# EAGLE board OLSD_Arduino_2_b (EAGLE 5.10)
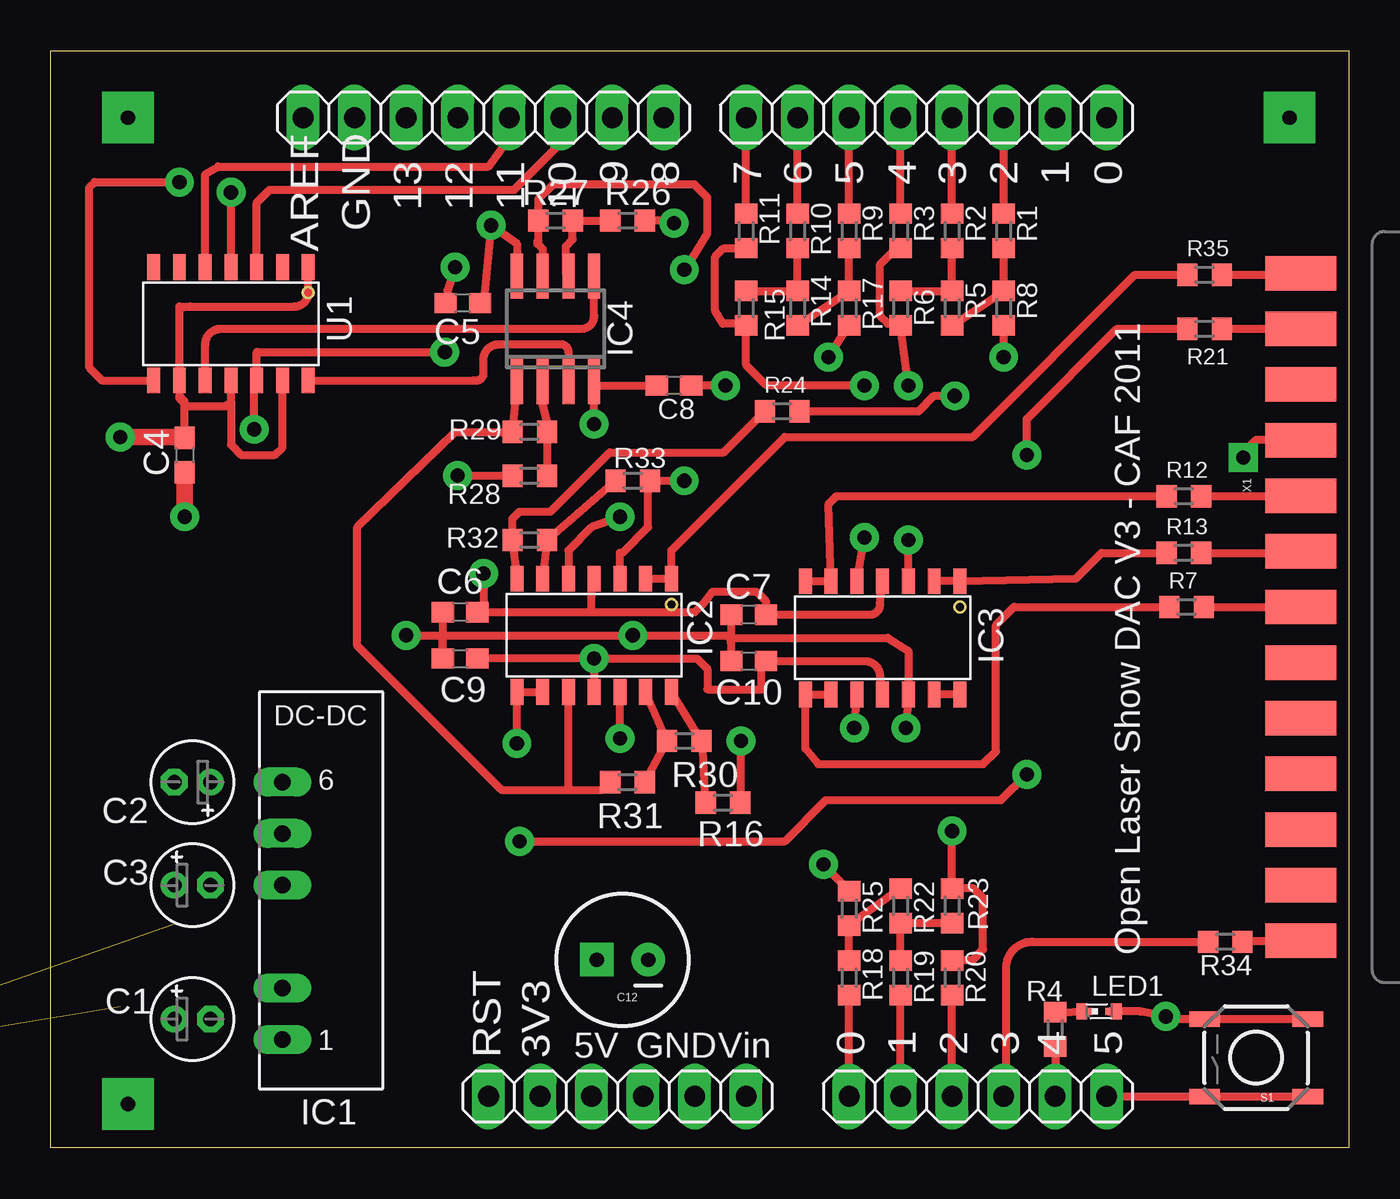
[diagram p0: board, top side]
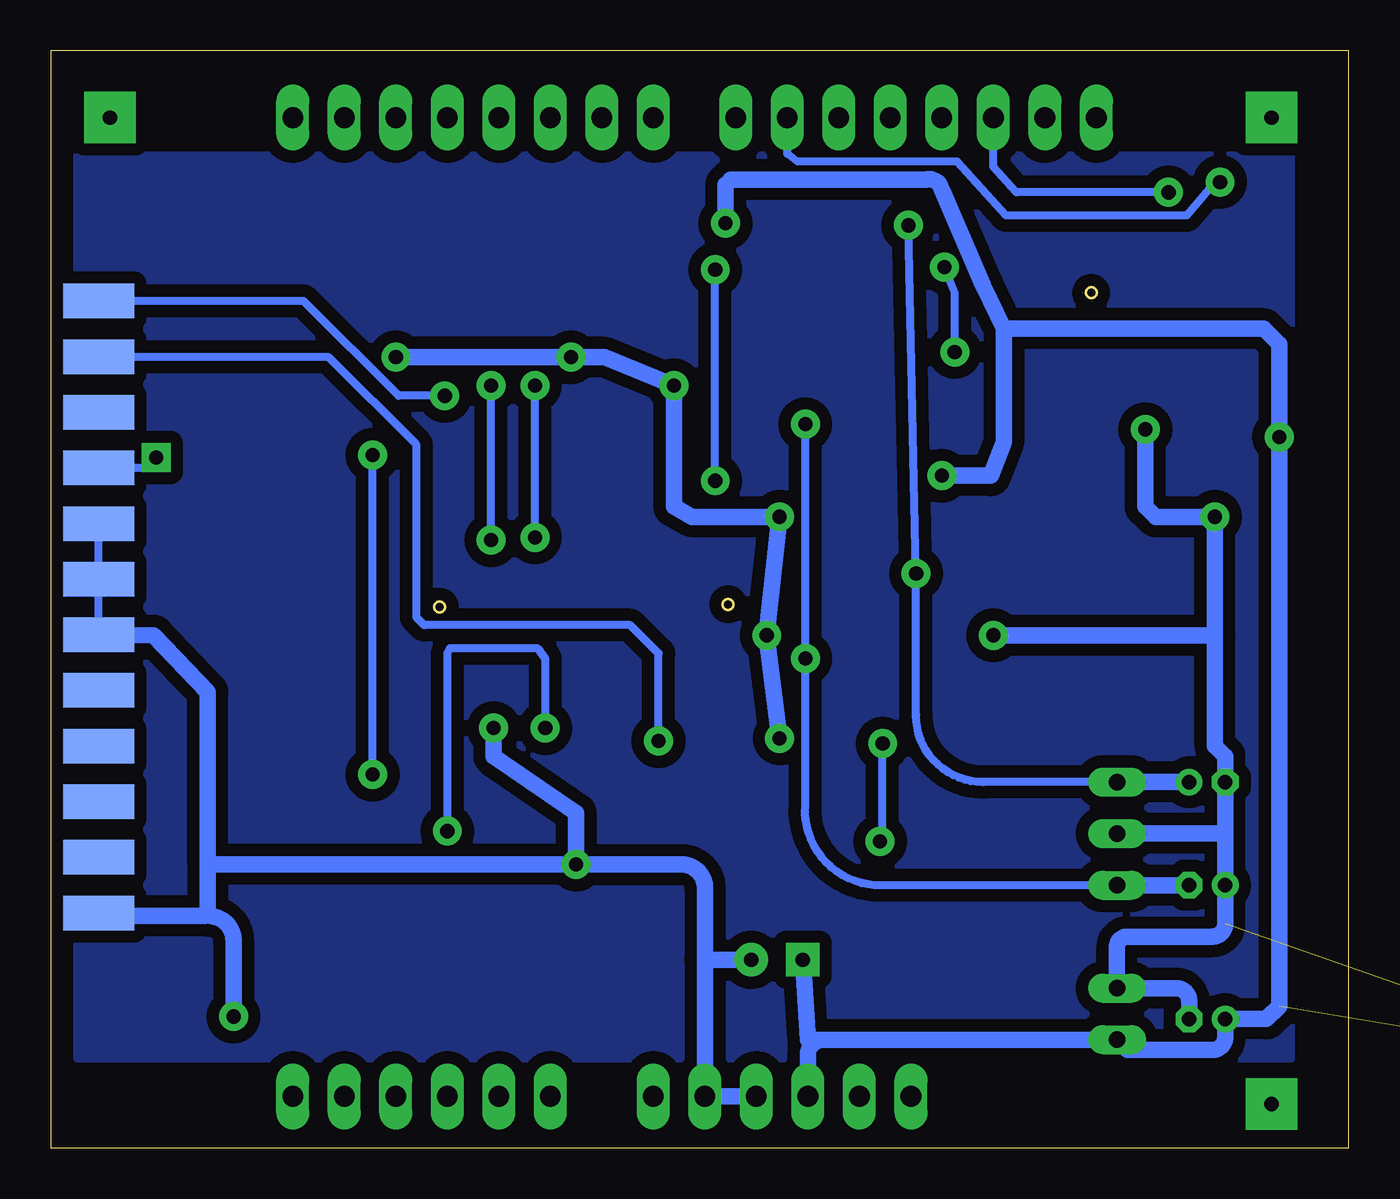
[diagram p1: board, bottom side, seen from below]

Size 64.01 x 54.1 mm. Coordinates in mm from the lower left corner, seen from the top.
Outline: 0,54.1 64.01,54.1 64.01,0 0,0 0,54.1
Copper layers (1*16): Top 0.035mm / dielectric 1.5mm / Bottom 0.035mm
Design rules "SparkFun": minimum track width 8mil, minimum drill 20mil, track to track 8mil, track to pad 8mil, pad to pad 8mil, via to via 8mil, smd to smd 8mil, copper to edge 10mil, drill to drill 8mil, minimum pad ring 12mil, minimum via ring 10mil, stop-mask expansion 4mil, vias tented up to drill 25mil, thermal gap 10mil

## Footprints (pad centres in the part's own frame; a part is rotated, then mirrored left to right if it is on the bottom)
E1,8-4 = drill 0.711 pad 1.168 round: + -0.889,0 | drill 0.711 pad 1.168 octagon: - 0.889,0
C0603 = smd 1.1 x 1: 1 -0.85,0; 2 0.85,0
CPOL-RADIAL-100UF-25V = drill 0.7 pad 1.651 square: 1 1.27,0 | drill 0.7 pad 1.651 round: 2 -1.27,0
NMA = drill 0.813 long: 1 0,6.35; 2 0,3.81; 4 0,-1.27; 5 0,-3.81; 6 0,-6.35
SOIC-14 = smd 1.27 x 0.635: 1 -0.762,-0.508; 2 -0.762,-1.778; 3 -0.762,-3.048; 4 -0.762,-4.318; 5 -0.762,-5.588; 6 -0.762,-6.858; 7 -0.762,-8.128; 8 4.826,-8.128; 9 4.826,-6.858; 10 4.826,-5.588; 11 4.826,-4.318; 12 4.826,-3.048; 13 4.826,-1.778; 14 4.826,-0.508
SO08 = smd 0.6 x 2.2: 1 -1.905,-2.6; 2 -0.635,-2.6; 3 0.635,-2.6; 4 1.905,-2.6; 5 1.905,2.6; 6 0.635,2.6; 7 -0.635,2.6; 8 -1.905,2.6
SMARTLED-TTW = smd 0.8 x 0.5: A 0,-0.875; C 0,0.875 | smd 0.35 x 0.35: A@1 0,-0.5; C@1 0,0.5
R0603 = smd 1 x 1.1: 1 -0.85,0; 2 0.85,0
TACTILE_SWITCH_SMD = smd 1.524 x 0.762: 1 -2.54,1.905; 2 2.54,1.905; 3 -2.54,-1.905; 4 2.54,-1.905
1X06 = drill 1.016 long: 1 -6.35,0; 2 -3.81,0; 3 -1.27,0; 4 1.27,0; 5 3.81,0; 6 6.35,0
1X08 = drill 1.016 long: 1 -8.89,0; 2 -6.35,0; 3 -3.81,0; 4 -1.27,0; 5 1.27,0; 6 3.81,0; 7 6.35,0; 8 8.89,0
F25D = smd 1.7 x 3.5: 1 -16.459,-6.045; 2 -13.716,-6.045; 3 -10.973,-6.045; 4 -8.23,-6.045; 5 -5.486,-6.045; 6 -2.743,-6.045; 7 0,-6.045; 8 2.743,-6.045; 9 5.486,-6.045; 10 8.23,-6.045; 11 10.973,-6.045; 12 13.716,-6.045; 13 16.459,-6.045 | smd 1.7 x 3.5 bottom: 14 -15.088,-6.045; 15 -12.344,-6.045; 16 -9.601,-6.045; 17 -6.858,-6.045; 18 -4.115,-6.045; 19 -1.372,-6.045; 20 1.372,-6.045; 21 4.115,-6.045; 22 6.858,-6.045; 23 9.601,-6.045; 24 12.344,-6.045; 25 15.088,-6.045

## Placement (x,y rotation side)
C1  4.7uF  [E1,8-4]  6.99,6.35 0 top
C2  4.7uF  [E1,8-4]  6.99,18.03 180 top
C3  4.7uF  [E1,8-4]  6.99,12.95 0 top
C4  0.1uF  [C0603]  6.6,34.16 270 top
C5  0.1uF  [C0603]  20.32,41.66 180 top
C6  0.1uF  [C0603]  20.19,26.42 180 top
C7  0.1uF  [C0603]  34.42,26.29 180 top
C8  0.1uF  [C0603]  30.73,37.59 180 top
C9  0.1uF  [C0603]  20.19,24.13 0 top
C10  0.1uF  [C0603]  34.42,24 0 top
C11  2200uF  [CPOL-RADIAL-100UF-25V]  not placed on the board
C12  100uF  [CPOL-RADIAL-100UF-25V]  28.19,9.27 180 top
IC1  VASD1-SIP  [NMA]  11.43,11.68 180 top
IC2  TL084  [SOIC-14]  31.12,27.3 270 top
IC3  TL084  [SOIC-14]  45.34,27.18 270 top
IC4  TL082D  [SO08]  24.89,40.39 0 top
LED1  Green  [SMARTLED-TTW]  51.69,6.73 270 top
R1  20K  [R0603]  46.99,45.21 270 top
R2  20K  [R0603]  44.45,45.21 270 top
R3  20K  [R0603]  41.91,45.21 270 top
R4  1K  [R0603]  49.53,5.84 90 top
R5  10K  [R0603]  44.45,41.4 270 top
R6  10K  [R0603]  41.91,41.4 90 top
R7  75R  [R0603]  56.01,26.67 0 top
R8  20K  [R0603]  46.99,41.4 270 top
R9  20K  [R0603]  39.37,45.21 270 top
R10  20K  [R0603]  36.83,45.21 270 top
R11  20K  [R0603]  34.29,45.21 270 top
R12  75R  [R0603]  55.88,32.13 0 top
R13  75R  [R0603]  55.88,29.34 0 top
R14  10K  [R0603]  36.83,41.4 270 top
R15  10K  [R0603]  34.29,41.4 90 top
R16  75R  [R0603]  33.15,17.02 0 top
R17  20K  [R0603]  39.37,41.4 270 top
R18  20K  [R0603]  39.37,8.38 90 top
R19  20K  [R0603]  41.91,8.38 90 top
R20  20K  [R0603]  44.45,8.38 90 top
R21  75R  [R0603]  56.9,40.39 0 top
R22  10K  [R0603]  41.91,11.94 90 top
R23  10K  [R0603]  44.45,11.94 270 top
R24  75R  [R0603]  36.07,36.32 0 top
R25  20K  [R0603]  39.37,11.81 90 top
R26  10K  [R0603]  28.45,45.72 180 top
R27  10K  [R0603]  24.89,45.72 180 top
R28  10K  [R0603]  23.62,33.15 0 top
R29  10K  [R0603]  23.62,35.31 180 top
R30  10K  [R0603]  31.24,20.07 0 top
R31  10K  [R0603]  28.45,18.03 0 top
R32  10K  [R0603]  23.62,29.97 180 top
R33  10K  [R0603]  28.7,32.89 180 top
R34  1K  [R0603]  57.91,10.16 0 top
R35  75R  [R0603]  56.9,43.05 0 top
S1  MINI 6X6MM SMD GW  [TACTILE_SWITCH_SMD]  59.44,4.45 180 top
U1  MCP4922  [SOIC-14]  13.21,42.67 270 top
U$1  POWER  [1X06]  27.94,2.54 0 top
U$2  ANALOG  [1X06]  45.72,2.54 0 top
U$3  DIGITAL_0_7  [1X08]  43.18,50.8 0 top
U$4  DIGITAL_8_13  [1X08]  21.34,50.8 0 top
X1  ILDA 25 Pin  [F25D]  67.69,26.67 270 top

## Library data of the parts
C1-C3 = rcl
C4-C10 = adafruit
C11 C12 S1 X1 = SparkFun
IC1 = dc-dc-converter
IC2 IC3 U1 = favreau
IC4 = linear
LED1 = led
R1-R35 = resistor
U$1-U$4 = arduino

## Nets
#LDAC: U1.8 U$4.7
+5V: C1.+ C4.1 C11.1 C12.1 IC1.1 R26.1 R28.1 U1.1 U1.9 U1.11 U1.13 U$1.3
+12V: C2.+ C5.1 C6.1 C7.1 IC1.6 IC2.4 IC3.4 IC4.8
-12V: C3.- C8.2 C9.2 C10.2 IC1.4 IC2.11 IC3.11 IC4.4
B1+: IC3.8 IC3.9 R7.1
B+: R7.2 X1.7
BLUE1: IC3.10 R20.2 R23.1
G1+: IC3.1 IC3.2 R13.1
G+: R13.2 X1.6
GND: C1.- C2.- C3.+ C4.2 C5.2 C6.2 C7.2 C8.1 C9.1 C10.1 C11.2 C12.2 IC1.2 IC1.5 IC2.5 IC2.12 IC3.12 LED1.C@1 R8.2 R17.2 R25.2 S1.3 S1.4 U1.12 U$1.4 U$1.5 X1.18 X1.19 X1.20 X1.25
GREEN1: IC3.3 R3.2 R6.1
INTERLOCK: X1.4 X1.17
MOSI: U1.5 U$4.5
N$1: R2.1 U$3.5
N$2: R9.1 U$3.3
N$3: R2.2 R5.1 R6.2
N$4: R1.1 U$3.6
N$5: R1.2 R5.2 R8.1
N$6: R3.1 U$3.4
N$7: R10.1 U$3.2
N$8: R11.1 U$3.1
N$9: R10.2 R14.1 R15.2
N$10: R9.2 R14.2 R17.1
N$11: R18.1 U$2.1
N$12: R19.1 U$2.2
N$13: R4.1 U$2.5
N$14: R19.2 R22.1 R23.2
N$15: R18.2 R22.2 R25.1
N$16: R20.1 U$2.3
N$17: R34.1 U$2.4
N$18: S1.1 S1.2 U$2.6
N$20: LED1.A@1 R4.2
N$24: IC4.5 U1.10
N$29: IC3.13 IC3.14
N$30: IC4.6 R26.2 R27.1
N$31: IC4.2 R28.2 R29.1
N$33: IC4.3 U1.14
N$35: IC2.6 R32.1 R33.2
N$36: IC2.13 R30.1 R31.2
R1+: IC3.6 IC3.7 R12.1
R+: R12.2 X1.5
RED1: IC3.5 R11.2 R15.1
SCK: U1.4 U$4.3
SHUTTER: R34.2 X1.13
SS: U1.3 U$4.6
X1+: IC2.1 IC2.2 R35.1
X1-: IC2.7 R24.1 R32.2
X2: IC2.10 IC4.1 R29.2 R31.1
X+: R35.2 X1.1
X-: R24.2 X1.14
Y1+: IC2.8 IC2.9 R21.1
Y1-: IC2.14 R16.1 R30.2
Y2: IC2.3 IC4.7 R27.2 R33.1
Y+: R21.2 X1.2
Y-: R16.2 X1.15

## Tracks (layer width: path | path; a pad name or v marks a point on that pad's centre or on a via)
#LDAC  (via drill 0.7 pad 1.42)
  Top 0.406: U1.8 2.54,37.85 1.91,38.48 1.91,47.37 2.16,47.62 v6.35,47.62
  Bottom 0.406: v6.35,47.62 6.6,47.62 8,45.97 16.89,45.97 19.3,48.64 27.18,48.64 27.69,49.02 U$4.7
+5V  (via drill 0.7 pad 1.42)  (1 unrouted)
  Top 0.406: 8.89,36.83 8.64,36.58 6.73,36.58 6.35,36.96 6.35,37.08 | 6.86,41.49 6.35,41.49 U1.9 | 6.86,41.49 12.03,41.49 arc90 12.7,42.16 U1.1 | v20.07,33.15 R28.1 | R26.1 30.73,45.72 v30.73,45.59 | U1.9 6.35,37.72 | 6.35,37.08 U1.9 | 8.89,36.83 U1.11 | 8.89,36.83 8.89,34.67 9.4,34.16 11.05,34.16 11.43,34.54 U1.13 | 6.86,41.49 6.44,41.4 | C4.1 6.6,36.83 6.35,37.08
  Top 0.813: v3.43,35.05 6.57,35.05 C4.1
  Bottom 0.406: 10.92,4.83 arc90 IC1.1 | 30.48,47.75 30.73,47.5
  Bottom 0.813: 10.92,4.83 6.73,4.83 arc-90 6.1,5.46 C1.+ 4.06,6.35 3.43,6.99 v3.43,35.05 3.43,39.62 4.19,40.39 17.02,40.39 | U$1.3 26.67,4.57 arc90 25.91,5.33 | 17.02,40.39 18.03,42.55 20.07,47.24 arc-90 20.83,47.75 30.48,47.75 | v20.07,33.15 17.65,33.15 17.02,34.8 17.02,40.39 | 30.73,47.5 v30.73,45.59 | IC1.1 25.91,5.33 | C12.1 26.67,5.33 25.91,5.33
+12V  (via drill 0.7 pad 1.42)
  Top 0.406: C5.1 21.34,41.66 v21.72,45.49 22.99,44.58 IC4.8 | IC3.4 40.89,26.8 arc-90 40.39,26.29 35.39,26.29 arc90 C7.1 35.27,26.96 34.8,27.43 32.64,27.43 32.13,26.8 31.75,26.42 26.67,26.42 | 21.46,26.42 C6.1 | 21.46,26.42 26.67,26.42 | 26.67,26.42 26.67,27.94 IC2.4 | 21.46,26.42 21.34,26.54 v21.34,28.32
  Bottom 0.406: v21.72,45.49 v21.34,28.32 21.34,21.34 arc-90 18.03,18.03 IC1.6
  Bottom 0.813: C2.+ IC1.6
-12V  (via drill 0.7 pad 1.42)
  Top 0.406: 26.99,37.59 arc-90 IC4.4 | 26.99,37.59 C8.2 | C10.2 40.13,24 arc-90 40.89,23.24 IC3.11 | C10.2 35.31,24 35.43,23.88 | v26.8,24.13 C9.2 | v26.8,24.13 31.88,24.13 32.38,23.62 32.38,22.61 35.05,22.61 35.05,23.79 C10.2 | v26.8,24.13 IC2.11 | 26.99,37.59 26.8,37.59 v26.8,35.69
  Bottom 0.406: IC1.4 23.37,12.95 arc90 26.8,16.89 v26.8,24.13 v26.8,35.69
  Bottom 0.813: C3.- IC1.4
B1+
  Top 0.406: IC3.9 IC3.8 37.21,19.68 37.85,18.92 45.97,18.92 46.61,19.56 46.61,25.78 47.5,26.67 R7.1
B+
  Top 0.406: R7.2 X1.7
BLUE1  (via drill 0.7 pad 1.42)
  Top 0.406: R20.2 44.49,9.27 45.47,9.27 45.97,9.78 45.97,12.32 45.5,12.79 R23.1 v44.45,15.62 | v39.62,20.7 IC3.10
  Bottom 0.406: v39.62,20.7 39.62,24.13 40,24.64 44.32,24.64 44.45,24.38 v44.45,15.62
G1+
  Top 0.406: IC3.2 IC3.1 50.55,28.07 51.82,29.34 R13.1
G+
  Top 0.406: 62.71,29.34 X1.6 61.57,29.34 R13.2
GND  (via drill 0.7 pad 1.42)  (1 unrouted)
  Top 0.406: v38.1,13.97 R25.2 | 19.56,41.66 C5.2 19.56,41.74 19.56,42.29 v19.94,43.43 | v33.27,37.59 C8.1 | v38.35,38.99 R17.2 | C7.2 C10.1 33.54,24.91 | 33.54,24.91 33.53,25.15 41.27,25.15 42.29,24.51 IC3.12 v42.16,20.7 | C9.1 C6.2 | 19.3,25.27 C9.1 | 19.3,25.27 v28.7,25.27 33.54,25.27 33.54,24.91 | C9.1 19.3,24.13 19.3,25.27 | v17.53,25.27 19.3,25.27 | IC2.5 25.53,29.46 26.67,30.61 v28.07,31.11 | v28.07,20.19 IC2.12 | S1.3 S1.4 55.12,6.35 v54.99,6.48 53.72,6.73 LED1.C@1 | v46.99,38.99 R8.2 | v10.03,35.43 10.03,37.72 U1.12 10.16,39.24 v19.43,39.24
  Top 0.813: v6.6,31.11 C4.2
  Bottom 0.406: 62.64,11.43 arc90 X1.25 | 56.13,11.43 56.39,11.43 56.26,11.56 | X1.18 X1.19 X1.20 | v46.99,38.99 47.12,38.99 | v19.43,39.24 19.43,42.16 v19.94,43.43
  Bottom 0.813: C1.- 7.87,7.24 arc-90 8.51,7.87 IC1.2 11.43,9.91 arc90 10.92,10.41 6.73,10.41 arc-90 6.1,11.05 C3.+ 6.1,15.49 | 6.1,15.49 C2.- 6.1,19.3 6.6,19.81 6.6,25.27 | v38.1,13.97 32.89,13.97 arc90 31.75,12.83 31.75,9.27 | v38.1,13.97 56.26,13.97 | 56.39,11.43 62.64,11.43 | 56.13,11.43 arc90 54.99,10.16 v54.99,6.48 | v38.1,13.97 38.1,16.51 42.16,19.3 v42.16,20.7 | X1.20 58.93,25.27 56.26,22.48 56.26,13.97 | 56.26,13.97 56.26,11.56 | v46.99,38.99 v38.35,38.99 36.7,38.99 v33.27,37.59 33.27,31.62 32.38,31.11 v28.07,31.11 v28.7,25.27 v28.07,20.19 | 6.1,15.49 IC1.5 | U$1.4 U$1.5 31.75,9.27 | 31.75,9.27 C12.2 | 6.6,25.27 v17.53,25.27 | 6.6,25.27 v6.6,31.11 9.52,31.11 10.03,31.62 v10.03,35.43
GREEN1  (via drill 0.7 pad 1.42)
  Top 0.406: R3.2 41.7,44.36 40.89,43.56 40.89,41.02 41.27,40.64 42.2,40.64 R6.1 v42.29,37.59 | IC3.3 v42.29,29.97
  Bottom 0.406: v42.29,29.97 v42.29,37.59
INTERLOCK  (via drill 0.7 pad 1.42)
  Top 0.406: 62.86,34.92 X1.4 62.76,34.92 59.44,34.92 59.05,34.54 v58.8,34.04
  Bottom 0.406: X1.17 59.18,33.53 v58.8,34.04
MOSI
  Top 0.406: U1.5 7.62,48.01 8.25,48.39 21.59,48.39 22.61,49.78 U$4.5
N$1
  Top 0.406: R2.1 U$3.5
N$2
  Top 0.406: R9.1 U$3.3
N$3
  Top 0.406: R2.2 R5.1 R6.2
N$4
  Top 0.406: R1.1 U$3.6
N$5
  Top 0.406: R1.2 R8.1 R5.2
N$6
  Top 0.406: R3.1 U$3.4
N$7
  Top 0.406: R10.1 U$3.2
N$8
  Top 0.406: R11.1 U$3.1
N$9
  Top 0.406: R10.2 R14.1 R15.2
N$10
  Top 0.406: R9.2 R17.1 R14.2
N$11
  Top 0.406: U$2.1 R18.1
N$12
  Top 0.406: U$2.2 R19.1
N$13
  Top 0.406: R4.1 U$2.5
N$14
  Top 0.406: R23.2 R22.1 R19.2
N$15
  Top 0.406: R18.2 R25.1 R22.2
N$16
  Top 0.406: U$2.3 R20.1
N$17
  Top 0.406: U$2.4 arc90 47.12,2.67 47.12,8.89 arc-90 48.39,10.16 R34.1
N$18
  Top 0.406: U$2.6 S1.2 S1.1
N$19  (via drill 0.7 pad 2.54)
  other vias: 3.81,50.8
N$20
  Top 0.406: R4.2 LED1.A@1
N$21  (via drill 0.7 pad 2.54)
  other vias: 61.09,50.8
N$22  (via drill 0.7 pad 2.54)
  other vias: 3.81,2.16
N$23
  pour Bottom (isolate 0.61): 2.79,49.02 2.79,4.32 62.74,4.32 62.74,49.02
N$24
  Top 0.406: IC4.5 26.8,41.02 arc-90 26.16,40.39 8.38,40.39 arc90 7.62,39.62 U1.10
N$29
  Top 0.406: 43.43,22.35 IC3.13 IC3.14
N$30
  Top 0.406: IC4.6 25.4,43.11 25.4,44.45 25.74,44.79 R27.1 R26.2
N$31
  Top 0.406: IC4.2 24.26,36.7 24.64,35.14 R29.1 R28.2
N$33
  Top 0.406: IC4.3 25.53,39.24 arc90 25.15,39.62 22.1,39.62 arc90 21.34,38.86 21.34,38.1 arc-90 20.83,37.85 U1.14
N$35
  Top 0.406: IC2.6 R32.1 R33.2
N$36
  Top 0.406: IC2.13 R30.1 R31.2
R1+
  Top 0.406: IC3.7 IC3.6 38.35,31.75 38.73,32.13 R12.1
R+
  Top 0.406: 62.76,32.13 X1.5 61.62,32.13 R12.2
RED1  (via drill 0.7 pad 1.42)
  Top 0.406: R11.2 33.19,44.36 32.77,43.94 32.77,41.27 33.15,40.64 34.2,40.64 R15.1 34.29,38.61 35.31,37.59 v40.13,37.59 | IC3.5 v40.13,30.1
  Bottom 0.406: v40.13,30.1 v40.13,37.59
SCK  (via drill 0.7 pad 1.42)
  Top 0.406: U1.4 v8.89,47.12
  Bottom 0.406: v8.89,47.12 16.38,47.12 17.53,48.39 U$4.3
SHUTTER
  Top 0.406: R34.2 arc-90 58.81,10.21 X1.13
SS
  Top 0.406: U1.3 10.16,46.61 10.79,47.24 22.86,47.24 25.15,49.53 U$4.6
X1+
  Top 0.406: IC2.2 IC2.1 30.61,29.46 36.2,35.05 45.47,35.05 53.47,43.05 R35.1
X1-
  Top 0.406: IC2.7 arc90 23.03,28.11 R32.2 22.77,31.03 23.11,31.37 24.64,31.37 27.56,34.29 33.19,34.29 R24.1
X2
  Top 0.406: IC4.1 arc-90 23.03,37.75 R29.2 19.94,35.31 15.11,30.61 15.11,24.77 22.23,17.65 25.53,17.65 | 25.53,17.65 27.22,17.65 R31.1 | 25.53,17.65 IC2.10
X+
  Top 0.406: 62.71,43.05 X1.1 61.57,43.05 R35.2
X-  (via drill 0.7 pad 1.42)
  Top 0.406: v44.58,37.08 43.56,37.08 42.8,36.32 R24.2
  Bottom 0.406: X1.14 51.54,41.76 46.86,37.08 v44.58,37.08
Y1+  (via drill 0.7 pad 1.42)
  Top 0.406: IC2.9 IC2.8 v22.99,19.94 | v23.11,15.11 36.2,15.11 38.23,17.14 46.86,17.14 v48.13,18.41 | v48.13,34.16 48.13,35.94 52.58,40.39 R21.1
  Bottom 0.406: v22.99,19.94 22.99,15.24 v23.11,15.11 | v48.13,18.41 v48.13,34.16
Y1-
  Top 0.406: IC2.14 R30.2 32.17,19.61 R16.1
Y2  (via drill 0.7 pad 1.42)
  Top 0.406: IC2.3 28.07,29.34 28.19,29.34 29.46,30.61 29.46,32.85 R33.1 v31.24,32.89 | v31.24,43.31 31.37,43.43 32.38,45.09 32.38,46.86 31.75,47.5 24.77,47.5 24.04,46.77 R27.2 24.04,44.74 24,44.7 24,44.58 24.26,44.32 IC4.7
  Bottom 0.406: v31.24,32.89 v31.24,43.31
Y+
  Top 0.406: R21.2 X1.2
Y-  (via drill 0.7 pad 1.42)
  Top 0.406: v34.04,20.07 34.04,16.98 R16.2
  Bottom 0.406: v34.04,20.07 34.04,24.38 35.43,25.78 45.59,25.78 45.97,26.16 45.97,34.67 50.29,38.99 62.76,38.99 X1.15

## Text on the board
tNames: 9 | 8 | 7 | 6 | 5 | 4 | 3 | 2 | 1 | 0 | 13 | 12 | 11 | 10 | GND | AREF | Open Laser Show DAC V3 - CAF 2011 | 0 | 1 | 2 | 3 | 4 | 5 | RST | 3V3 | 5V | GND | Vin
TallParts: USB | ISP | PWR
ArduinoHoles: 3.2mm | 2.2mm | 3.2mm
